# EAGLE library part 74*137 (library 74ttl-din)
3-line to 8-line DECODER/DEMULTIPLEXER, address LATCH
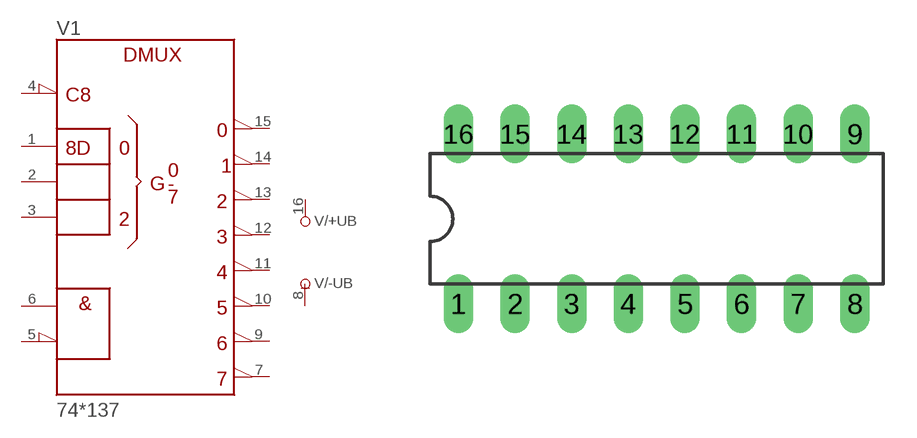
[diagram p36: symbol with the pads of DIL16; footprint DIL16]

Designator prefix V; gates /+UB=+UB /-UB=-UB 1=137

## 74137N  [DIL16]
1  1:A  in
2  1:B  in
3  1:C  in
4  1:GL\  in
5  1:G\2  in
6  1:G1  in
7  1:Y7  out
8  /-UB:-UB  pwr
9  1:Y6  out
10  1:Y5  out
11  1:Y4  out
12  1:Y3  out
13  1:Y2  out
14  1:Y1  out
15  1:Y0  out
16  /+UB:+UB  pwr

## Footprint DIL16 (pad centres in mm)
Dual In Line Package
drill 0.813 long: 1 -8.89,-3.81; 2 -6.35,-3.81; 3 -3.81,-3.81; 4 -1.27,-3.81; 5 1.27,-3.81; 6 3.81,-3.81; 7 6.35,-3.81; 8 8.89,-3.81; 9 8.89,3.81; 10 6.35,3.81; 11 3.81,3.81; 12 1.27,3.81; 13 -1.27,3.81; 14 -3.81,3.81; 15 -6.35,3.81; 16 -8.89,3.81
